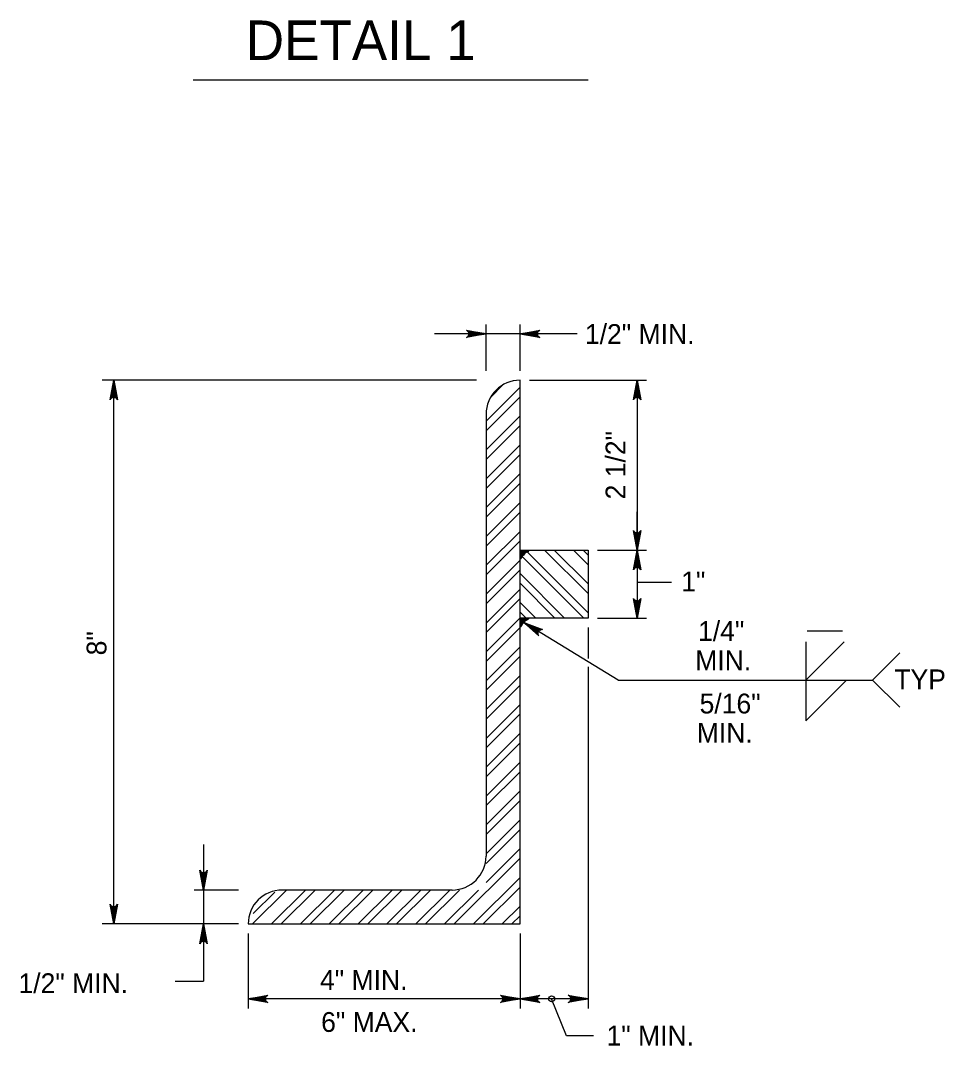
# Model space of a CAD drawing. Extents: x 2087776 to 2104538, y 970919 to 982612.
# Drawn here: x 2094874 to 2095333, y 975670 to 976178 of the extents above; entities that cross this region are included whole.
import ezdxf

# ---------------------------------------------------------------- set-up
doc = ezdxf.new("R2010")
doc.units = 0
doc.layers.add('1', color=7, linetype='Continuous')

msp = doc.modelspace()

# ---------------------------------------------------------------- linework, layer by layer
at = {"layer": '1'}
for p, q in [((2094959.82, 976148.99), (2095155.82, 976148.99)), ((2095105.2, 976004.55), (2095105.2, 976027.5)), ((2095122.07, 976004.55), (2095122.07, 976027.5)), ((2095150.41, 976022.77), (2095079.66, 976022.77)), ((2095100.47, 975999.82), (2094914.62, 975999.82)), ((2094920.39, 975729.88), (2094920.39, 975999.82)), ((2095122.07, 975729.88), (2095122.07, 975999.82)), ((2095126.79, 975999.82), (2095184.86, 975999.82)), ((2095180.13, 975999.82), (2095180.13, 975915.47)), ((2095105.2, 975982.95), (2095105.2, 975763.62)), ((2095180.13, 975915.47), (2095180.13, 975934.46)), ((2095122.07, 975915.47), (2095122.07, 975915.47)), ((2095160.54, 975915.47), (2095184.86, 975915.47)), ((2095180.13, 975915.47), (2095180.13, 975902.66)), ((2095180.13, 975902.66), (2095180.13, 975881.72)), ((2095180.13, 975899.58), (2095197.3, 975899.58)), ((2095160.54, 975881.72), (2095184.86, 975881.72)), ((2095155.81, 975877), (2095155.81, 975861.74)), ((2095264.52, 975875.43), (2095282.11, 975875.43)), ((2095263.93, 975850.97), (2095282.96, 975869.99)), ((2095263.93, 975869.99), (2095263.93, 975850.97)), ((2095155.81, 975857.54), (2095155.81, 975687.99)), ((2095170.73, 975850.97), (2095297, 975850.97)), ((2095263.93, 975850.97), (2095263.93, 975830.72)), ((2095263.93, 975830.72), (2095284.18, 975850.97)), ((2094982.37, 975746.75), (2094960.28, 975746.75)), ((2095088.33, 975746.75), (2095003.98, 975746.75)), ((2094982.37, 975729.88), (2094914.62, 975729.88)), ((2094982.37, 975729.88), (2094960.28, 975729.88)), ((2094987.11, 975729.88), (2095122.07, 975729.88)), ((2094987.09, 975725.15), (2094987.09, 975687.99)), ((2095122.07, 975725.15), (2095122.07, 975687.99)), ((2095081.14, 975692.72), (2094987.09, 975692.72)), ((2095122.07, 975692.72), (2095081.14, 975692.72)), ((2095122.07, 975692.72), (2095093.73, 975692.72)), ((2095155.81, 975692.72), (2095122.07, 975692.72))]:
    msp.add_line(p, q, dxfattribs=at)
for points in [[(2095105.2, 976022.77), (2095095.41, 976020.94), (2095095.79, 976021.2), (2095096.17, 976021.46), (2095096.36, 976021.79), (2095096.56, 976022.11), (2095096.61, 976022.44), (2095096.67, 976022.77), (2095096.61, 976023.1), (2095096.56, 976023.43), (2095096.36, 976023.76), (2095096.17, 976024.08), (2095095.79, 976024.34), (2095095.41, 976024.61), (2095105.2, 976022.77), (2095095.79, 976024.34), (2095096.17, 976024.08), (2095105.2, 976022.77), (2095096.36, 976023.76), (2095096.56, 976023.43), (2095105.2, 976022.77), (2095096.61, 976023.1), (2095096.67, 976022.77), (2095105.2, 976022.77), (2095096.61, 976022.44), (2095096.56, 976022.11), (2095105.2, 976022.77), (2095096.36, 976021.79), (2095096.17, 976021.46), (2095105.2, 976022.77), (2095095.79, 976021.2)], [(2095122.07, 976022.77), (2095131.86, 976024.61), (2095131.48, 976024.34), (2095131.11, 976024.08), (2095130.91, 976023.76), (2095130.72, 976023.43), (2095130.66, 976023.1), (2095130.6, 976022.77), (2095130.66, 976022.44), (2095130.72, 976022.11), (2095130.91, 976021.79), (2095131.11, 976021.46), (2095131.48, 976021.2), (2095131.86, 976020.94), (2095122.07, 976022.77), (2095131.48, 976021.2), (2095131.11, 976021.46), (2095122.07, 976022.77), (2095130.91, 976021.79), (2095130.72, 976022.11), (2095122.07, 976022.77), (2095130.66, 976022.44), (2095130.6, 976022.77), (2095122.07, 976022.77), (2095130.66, 976023.1), (2095130.72, 976023.43), (2095122.07, 976022.77), (2095130.91, 976023.76), (2095131.11, 976024.08), (2095122.07, 976022.77), (2095131.48, 976024.34)], [(2094920.39, 975999.82), (2094922.22, 975990.04), (2094921.96, 975990.42), (2094921.7, 975990.79), (2094921.37, 975990.99), (2094921.05, 975991.18), (2094920.72, 975991.24), (2094920.39, 975991.29), (2094920.06, 975991.24), (2094919.73, 975991.18), (2094919.41, 975990.99), (2094919.08, 975990.79), (2094918.82, 975990.42), (2094918.55, 975990.04), (2094920.39, 975999.82), (2094918.82, 975990.42), (2094919.08, 975990.79), (2094920.39, 975999.82), (2094919.41, 975990.99), (2094919.73, 975991.18), (2094920.39, 975999.82), (2094920.06, 975991.24), (2094920.39, 975991.29), (2094920.39, 975999.82), (2094920.72, 975991.24), (2094921.05, 975991.18), (2094920.39, 975999.82), (2094921.37, 975990.99), (2094921.7, 975990.79), (2094920.39, 975999.82), (2094921.96, 975990.42)], [(2095180.13, 975999.82), (2095181.97, 975990.04), (2095181.71, 975990.42), (2095181.44, 975990.79), (2095181.12, 975990.99), (2095180.79, 975991.18), (2095180.46, 975991.24), (2095180.13, 975991.29), (2095179.8, 975991.24), (2095179.48, 975991.18), (2095179.15, 975990.99), (2095178.82, 975990.79), (2095178.56, 975990.42), (2095178.3, 975990.04), (2095180.13, 975999.82), (2095178.56, 975990.42), (2095178.82, 975990.79), (2095180.13, 975999.82), (2095179.15, 975990.99), (2095179.48, 975991.18), (2095180.13, 975999.82), (2095179.8, 975991.24), (2095180.13, 975991.29), (2095180.13, 975999.82), (2095180.46, 975991.24), (2095180.79, 975991.18), (2095180.13, 975999.82), (2095181.12, 975990.99), (2095181.44, 975990.79), (2095180.13, 975999.82), (2095181.71, 975990.42)], [(2095105.2, 975979.51), (2095122.07, 975996.37)], [(2095107.4, 975991.28), (2095113.74, 975997.62)], [(2095105.2, 975974.73), (2095122.07, 975991.6)], [(2095105.2, 975965.19), (2095122.07, 975982.06)], [(2095105.2, 975960.42), (2095122.07, 975977.29)], [(2095105.2, 975950.87), (2095122.07, 975967.74)], [(2095105.2, 975946.1), (2095122.07, 975962.97)], [(2095105.2, 975936.56), (2095122.07, 975953.43)], [(2095105.2, 975931.78), (2095122.07, 975948.66)], [(2095105.2, 975922.24), (2095122.07, 975939.11)], [(2095105.2, 975917.47), (2095122.07, 975934.34)], [(2095105.2, 975907.93), (2095122.07, 975924.8)], [(2095180.13, 975915.47), (2095178.3, 975925.25), (2095178.56, 975924.88), (2095178.82, 975924.5), (2095179.15, 975924.3), (2095179.48, 975924.11), (2095179.8, 975924.05), (2095180.13, 975924), (2095180.46, 975924.05), (2095180.79, 975924.11), (2095181.12, 975924.3), (2095181.44, 975924.5), (2095181.71, 975924.88), (2095181.97, 975925.25), (2095180.13, 975915.47), (2095181.71, 975924.88), (2095181.44, 975924.5), (2095180.13, 975915.47), (2095181.12, 975924.3), (2095180.79, 975924.11), (2095180.13, 975915.47), (2095180.46, 975924.05), (2095180.13, 975924), (2095180.13, 975915.47), (2095179.8, 975924.05), (2095179.48, 975924.11), (2095180.13, 975915.47), (2095179.15, 975924.3), (2095178.82, 975924.5), (2095180.13, 975915.47), (2095178.56, 975924.88)], [(2095105.2, 975903.15), (2095122.07, 975920.02)], [(2095155.81, 975881.72), (2095122.07, 975881.72), (2095122.07, 975915.47), (2095155.81, 975915.47), (2095155.81, 975881.72)], [(2095153.72, 975881.72), (2095122.07, 975913.36)], [(2095122.28, 975910.99), (2095122.28, 975915.21), (2095126.5, 975915.21), (2095125.85, 975914.69), (2095125.36, 975914.42), (2095124.81, 975914.12), (2095124.21, 975913.65), (2095123.73, 975913.01), (2095123.16, 975912.42), (2095122.64, 975911.66), (2095122.23, 975911.07), (2095122.51, 975915.13), (2095122.8, 975912.21), (2095122.98, 975915.09), (2095123.33, 975912.8), (2095123.47, 975915.05), (2095123.83, 975913.42), (2095124.04, 975915.15), (2095124.4, 975913.96), (2095124.71, 975915.15), (2095125.04, 975914.33), (2095125.2, 975915.09), (2095125.43, 975914.58), (2095125.59, 975915.09), (2095125.81, 975914.86), (2095126.16, 975915.02), (2095122.41, 975915), (2095122.62, 975911.87), (2095123.68, 975913.52), (2095125.28, 975914.56), (2095122.59, 975914.71)], [(2095155.81, 975884.4), (2095124.74, 975915.47)], [(2095155.81, 975893.94), (2095134.28, 975915.47)], [(2095155.81, 975898.71), (2095139.06, 975915.47)], [(2095155.81, 975908.25), (2095148.6, 975915.47)], [(2095155.81, 975913.03), (2095153.37, 975915.47)], [(2095180.13, 975915.47), (2095181.97, 975905.68), (2095181.71, 975906.06), (2095181.44, 975906.44), (2095181.12, 975906.63), (2095180.79, 975906.83), (2095180.46, 975906.88), (2095180.13, 975906.94), (2095179.8, 975906.88), (2095179.48, 975906.83), (2095179.15, 975906.63), (2095178.82, 975906.44), (2095178.56, 975906.06), (2095178.3, 975905.68), (2095180.13, 975915.47), (2095178.56, 975906.06), (2095178.82, 975906.44), (2095180.13, 975915.47), (2095179.15, 975906.63), (2095179.48, 975906.83), (2095180.13, 975915.47), (2095179.8, 975906.88), (2095180.13, 975906.94), (2095180.13, 975915.47), (2095180.46, 975906.88), (2095180.79, 975906.83), (2095180.13, 975915.47), (2095181.12, 975906.63), (2095181.44, 975906.44), (2095180.13, 975915.47), (2095181.71, 975906.06)], [(2095105.2, 975893.6), (2095122.07, 975910.48)], [(2095105.2, 975888.83), (2095122.07, 975905.7)], [(2095144.17, 975881.72), (2095122.07, 975903.82)], [(2095105.2, 975879.29), (2095122.07, 975896.16)], [(2095139.39, 975881.72), (2095122.07, 975899.05)], [(2095105.2, 975874.52), (2095122.07, 975891.39)], [(2095180.13, 975881.72), (2095178.3, 975891.51), (2095178.56, 975891.13), (2095178.82, 975890.75), (2095179.15, 975890.56), (2095179.48, 975890.36), (2095179.8, 975890.31), (2095180.13, 975890.25), (2095180.46, 975890.31), (2095180.79, 975890.36), (2095181.12, 975890.56), (2095181.44, 975890.75), (2095181.71, 975891.13), (2095181.97, 975891.51), (2095180.13, 975881.72), (2095181.71, 975891.13), (2095181.44, 975890.75), (2095180.13, 975881.72), (2095181.12, 975890.56), (2095180.79, 975890.36), (2095180.13, 975881.72), (2095180.46, 975890.31), (2095180.13, 975890.25), (2095180.13, 975881.72), (2095179.8, 975890.31), (2095179.48, 975890.36), (2095180.13, 975881.72), (2095179.15, 975890.56), (2095178.82, 975890.75), (2095180.13, 975881.72), (2095178.56, 975891.13)], [(2095129.85, 975881.72), (2095122.07, 975889.5)], [(2095105.2, 975864.98), (2095122.07, 975881.85)], [(2095125.08, 975881.72), (2095122.07, 975884.73)], [(2095122.28, 975877.3), (2095122.28, 975881.52), (2095126.5, 975881.52), (2095125.85, 975880.99), (2095125.36, 975880.74), (2095124.82, 975880.42), (2095124.22, 975879.96), (2095123.73, 975879.32), (2095123.16, 975878.72), (2095122.65, 975877.97), (2095122.23, 975877.38), (2095122.51, 975881.43), (2095122.8, 975878.51), (2095122.98, 975881.41), (2095123.34, 975879.11), (2095123.47, 975881.35), (2095123.83, 975879.73), (2095124.04, 975881.46), (2095124.4, 975880.26), (2095124.71, 975881.46), (2095125.05, 975880.63), (2095125.2, 975881.41), (2095125.43, 975880.89), (2095125.59, 975881.41), (2095125.82, 975881.17), (2095126.16, 975881.33), (2095122.41, 975881.3), (2095122.62, 975878.18), (2095123.68, 975879.83), (2095125.28, 975880.86), (2095122.59, 975881.02)], [(2095105.2, 975860.2), (2095122.07, 975877.08)], [(2095170.73, 975850.97), (2095123.91, 975879.56)], [(2095123.91, 975879.56), (2095133.22, 975876.02), (2095132.76, 975876), (2095132.3, 975875.97), (2095131.97, 975875.79), (2095131.63, 975875.61), (2095131.41, 975875.36), (2095131.19, 975875.11), (2095131.07, 975874.8), (2095130.95, 975874.49), (2095130.94, 975874.11), (2095130.94, 975873.73), (2095131.12, 975873.31), (2095131.31, 975872.89), (2095123.91, 975879.56), (2095131.12, 975873.31), (2095130.94, 975873.73), (2095123.91, 975879.56), (2095130.94, 975874.11), (2095130.95, 975874.49), (2095123.91, 975879.56), (2095131.07, 975874.8), (2095131.19, 975875.11), (2095123.91, 975879.56), (2095131.41, 975875.36), (2095131.63, 975875.61), (2095123.91, 975879.56), (2095131.97, 975875.79), (2095132.3, 975875.97), (2095123.91, 975879.56), (2095132.76, 975876)], [(2095105.2, 975850.66), (2095122.07, 975867.53)], [(2095105.2, 975845.89), (2095122.07, 975862.76)], [(2095310.5, 975864.46), (2095297, 975850.97), (2095310.5, 975837.47)], [(2095105.2, 975836.34), (2095122.07, 975853.22)], [(2095105.2, 975831.57), (2095122.07, 975848.44)], [(2095105.2, 975822.02), (2095122.07, 975838.9)], [(2095105.2, 975817.25), (2095122.07, 975834.13)], [(2095105.2, 975807.71), (2095122.07, 975824.58)], [(2095105.2, 975802.93), (2095122.07, 975819.81)], [(2095105.2, 975793.39), (2095122.07, 975810.26)], [(2095105.2, 975788.62), (2095122.07, 975805.49)], [(2095105.2, 975779.08), (2095122.07, 975795.95)], [(2095105.2, 975774.31), (2095122.07, 975791.18)], [(2095105.2, 975764.76), (2095122.07, 975781.64)], [(2095105.2, 975759.99), (2095122.07, 975776.86)], [(2094965.01, 975769.32), (2094965.01, 975701.53)], [(2095105.2, 975750.44), (2095122.07, 975767.31)], [(2095089.4, 975729.88), (2095122.07, 975762.55)], [(2094965.01, 975746.75), (2094963.17, 975756.53), (2094963.43, 975756.16), (2094963.7, 975755.78), (2094964.02, 975755.58), (2094964.35, 975755.39), (2094964.68, 975755.33), (2094965.01, 975755.28), (2094965.34, 975755.33), (2094965.66, 975755.39), (2094965.99, 975755.58), (2094966.32, 975755.78), (2094966.58, 975756.16), (2094966.84, 975756.53), (2094965.01, 975746.75), (2094966.58, 975756.16), (2094966.32, 975755.78), (2094965.01, 975746.75), (2094965.99, 975755.58), (2094965.66, 975755.39), (2094965.01, 975746.75), (2094965.34, 975755.33), (2094965.01, 975755.28), (2094965.01, 975746.75), (2094964.68, 975755.33), (2094964.35, 975755.39), (2094965.01, 975746.75), (2094964.02, 975755.58), (2094963.7, 975755.78), (2094965.01, 975746.75), (2094963.43, 975756.16)], [(2095098.94, 975729.88), (2095122.07, 975753)], [(2094989.19, 975729.88), (2095006.06, 975746.75)], [(2094989.55, 975735.01), (2095000.27, 975745.73)], [(2094998.73, 975729.88), (2095015.6, 975746.75)], [(2095003.51, 975729.88), (2095020.38, 975746.75)], [(2095013.05, 975729.88), (2095029.92, 975746.75)], [(2095017.82, 975729.88), (2095034.69, 975746.75)], [(2095027.36, 975729.88), (2095044.23, 975746.75)], [(2095032.14, 975729.88), (2095049.01, 975746.75)], [(2095041.68, 975729.88), (2095058.55, 975746.75)], [(2095046.46, 975729.88), (2095063.33, 975746.75)], [(2095056, 975729.88), (2095072.88, 975746.75)], [(2095060.77, 975729.88), (2095077.64, 975746.75)], [(2095070.32, 975729.88), (2095087.19, 975746.75)], [(2095075.09, 975729.88), (2095091.96, 975746.75)], [(2095084.63, 975729.88), (2095101.5, 975746.75)], [(2095103.72, 975729.88), (2095122.07, 975748.22)], [(2094920.39, 975729.88), (2094918.55, 975739.66), (2094918.82, 975739.29), (2094919.08, 975738.91), (2094919.41, 975738.71), (2094919.73, 975738.52), (2094920.06, 975738.46), (2094920.39, 975738.41), (2094920.72, 975738.46), (2094921.05, 975738.52), (2094921.37, 975738.71), (2094921.7, 975738.91), (2094921.96, 975739.29), (2094922.22, 975739.66), (2094920.39, 975729.88), (2094921.96, 975739.29), (2094921.7, 975738.91), (2094920.39, 975729.88), (2094921.37, 975738.71), (2094921.05, 975738.52), (2094920.39, 975729.88), (2094920.72, 975738.46), (2094920.39, 975738.41), (2094920.39, 975729.88), (2094920.06, 975738.46), (2094919.73, 975738.52), (2094920.39, 975729.88), (2094919.41, 975738.71), (2094919.08, 975738.91), (2094920.39, 975729.88), (2094918.82, 975739.29)], [(2095113.26, 975729.88), (2095122.07, 975738.68)], [(2095118.03, 975729.88), (2095122.07, 975733.91)], [(2094965.01, 975729.88), (2094966.84, 975720.09), (2094966.58, 975720.47), (2094966.32, 975720.85), (2094965.99, 975721.04), (2094965.66, 975721.23), (2094965.34, 975721.29), (2094965.01, 975721.35), (2094964.68, 975721.29), (2094964.35, 975721.23), (2094964.02, 975721.04), (2094963.7, 975720.85), (2094963.43, 975720.47), (2094963.17, 975720.09), (2094965.01, 975729.88), (2094963.43, 975720.47), (2094963.7, 975720.85), (2094965.01, 975729.88), (2094964.02, 975721.04), (2094964.35, 975721.23), (2094965.01, 975729.88), (2094964.68, 975721.29), (2094965.01, 975721.35), (2094965.01, 975729.88), (2094965.34, 975721.29), (2094965.66, 975721.23), (2094965.01, 975729.88), (2094965.99, 975721.04), (2094966.32, 975720.85), (2094965.01, 975729.88), (2094966.58, 975720.47)], [(2094950.83, 975701.53), (2094965.01, 975701.53)], [(2094987.09, 975692.72), (2094996.88, 975694.55), (2094996.5, 975694.29), (2094996.13, 975694.03), (2094995.93, 975693.7), (2094995.74, 975693.37), (2094995.68, 975693.05), (2094995.62, 975692.72), (2094995.68, 975692.39), (2094995.74, 975692.06), (2094995.93, 975691.73), (2094996.13, 975691.41), (2094996.5, 975691.14), (2094996.88, 975690.88), (2094987.09, 975692.72), (2094996.5, 975691.14), (2094996.13, 975691.41), (2094987.09, 975692.72), (2094995.93, 975691.73), (2094995.74, 975692.06), (2094987.09, 975692.72), (2094995.68, 975692.39), (2094995.62, 975692.72), (2094987.09, 975692.72), (2094995.68, 975693.05), (2094995.74, 975693.37), (2094987.09, 975692.72), (2094995.93, 975693.7), (2094996.13, 975694.03), (2094987.09, 975692.72), (2094996.5, 975694.29)], [(2095122.07, 975692.72), (2095112.29, 975690.88), (2095112.67, 975691.14), (2095113.04, 975691.41), (2095113.24, 975691.73), (2095113.43, 975692.06), (2095113.49, 975692.39), (2095113.54, 975692.72), (2095113.49, 975693.05), (2095113.43, 975693.37), (2095113.24, 975693.7), (2095113.04, 975694.03), (2095112.67, 975694.29), (2095112.29, 975694.55), (2095122.07, 975692.72), (2095112.67, 975694.29), (2095113.04, 975694.03), (2095122.07, 975692.72), (2095113.24, 975693.7), (2095113.43, 975693.37), (2095122.07, 975692.72), (2095113.49, 975693.05), (2095113.54, 975692.72), (2095122.07, 975692.72), (2095113.49, 975692.39), (2095113.43, 975692.06), (2095122.07, 975692.72), (2095113.24, 975691.73), (2095113.04, 975691.41), (2095122.07, 975692.72), (2095112.67, 975691.14)], [(2095122.07, 975692.72), (2095131.86, 975694.55), (2095131.48, 975694.29), (2095131.11, 975694.03), (2095130.91, 975693.7), (2095130.72, 975693.37), (2095130.66, 975693.05), (2095130.6, 975692.72), (2095130.66, 975692.39), (2095130.72, 975692.06), (2095130.91, 975691.73), (2095131.11, 975691.41), (2095131.48, 975691.14), (2095131.86, 975690.88), (2095122.07, 975692.72), (2095131.48, 975691.14), (2095131.11, 975691.41), (2095122.07, 975692.72), (2095130.91, 975691.73), (2095130.72, 975692.06), (2095122.07, 975692.72), (2095130.66, 975692.39), (2095130.6, 975692.72), (2095122.07, 975692.72), (2095130.66, 975693.05), (2095130.72, 975693.37), (2095122.07, 975692.72), (2095130.91, 975693.7), (2095131.11, 975694.03), (2095122.07, 975692.72), (2095131.48, 975694.29)], [(2095158.57, 975674.39), (2095145.07, 975674.39), (2095137.74, 975692.72)], [(2095155.81, 975692.72), (2095146.03, 975690.88), (2095146.41, 975691.14), (2095146.78, 975691.41), (2095146.98, 975691.73), (2095147.17, 975692.06), (2095147.23, 975692.39), (2095147.28, 975692.72), (2095147.23, 975693.05), (2095147.17, 975693.37), (2095146.98, 975693.7), (2095146.78, 975694.03), (2095146.41, 975694.29), (2095146.03, 975694.55), (2095155.81, 975692.72), (2095146.41, 975694.29), (2095146.78, 975694.03), (2095155.81, 975692.72), (2095146.98, 975693.7), (2095147.17, 975693.37), (2095155.81, 975692.72), (2095147.23, 975693.05), (2095147.28, 975692.72), (2095155.81, 975692.72), (2095147.23, 975692.39), (2095147.17, 975692.06), (2095155.81, 975692.72), (2095146.98, 975691.73), (2095146.78, 975691.41), (2095155.81, 975692.72), (2095146.41, 975691.14)]]:
    msp.add_lwpolyline(points, dxfattribs=at)
msp.add_circle((2095137.73, 975692.72), 1.5, dxfattribs=at)
for centre, start, end in [((2095122.07, 975982.95), 90, 180), ((2095088.33, 975763.62), 270, 0), ((2095003.98, 975729.88), 90, 180)]:
    msp.add_arc(centre, 16.87, start, end, dxfattribs=at)

# ---------------------------------------------------------------- texts
for s, height, p in [('DETAIL 1', 19.685, (2094985.94, 976158.7)), ('1/2" MIN.', 9.843, (2095154.26, 976017.81)), ('1"', 9.843, (2095202.06, 975894.97)), ('1/4"', 9.843, (2095210.43, 975870.39)), ('MIN.', 9.843, (2095209.03, 975855.83)), ('TYP', 9.843, (2095307.85, 975846.38)), ('5/16"', 9.843, (2095211.19, 975834.4)), ('MIN.', 9.843, (2095209.8, 975819.84)), ('1/2" MIN.', 9.843, (2094873.1, 975695.55)), ('4" MIN.', 9.843, (2095022.76, 975697.16)), ('6" MAX.', 9.843, (2095023.33, 975676.31)), ('1" MIN.', 9.843, (2095164.98, 975669.56))]:
    msp.add_text(s, height=height, dxfattribs=at).set_placement(p)
for s, p in [('2 1/2"', (2095174.37, 975940.66)), ('8"', (2094916.77, 975863.24))]:
    msp.add_text(s, height=9.843, rotation=90, dxfattribs=at).set_placement(p)

doc.saveas('drawing.dxf')
